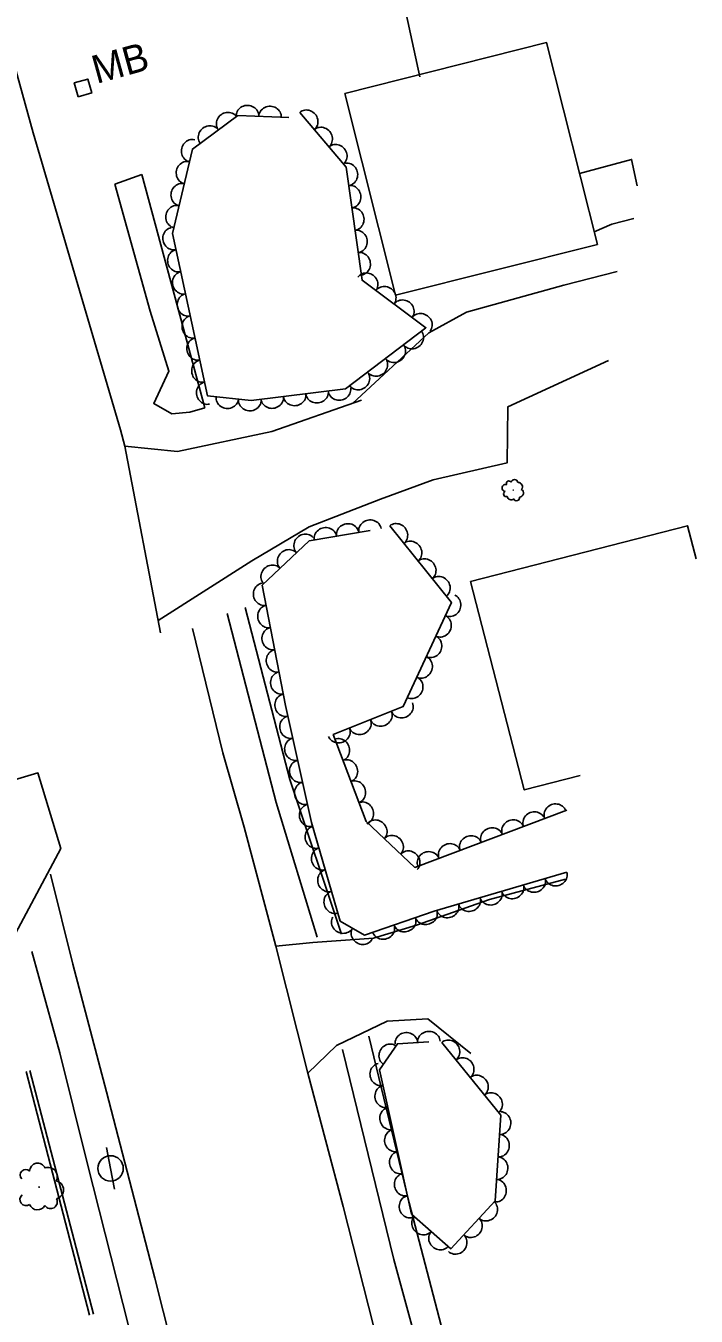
# Model space of a CAD drawing. Extents: x 1722896 to 1754269, y 648279 to 666297.
# Drawn here: x 1726025 to 1726143.8, y 664330.2 to 664558.8 of the extents above; entities that cross this region are included whole.
import ezdxf

# ---------------------------------------------------------------- set-up
doc = ezdxf.new("R2010")
doc.units = 0
for name, color, linetype in [('DESIGN - CENTERLINE - Proposed Text', 7, 'Continuous'), ('SURVEY - CENTERLINE - Preliminary', 7, 'Continuous'), ('SURVEY - CENTERLINE - Preliminary Text', 7, 'Continuous'), ('SURVEY - DTM - Breaklines', 7, 'Continuous'), ('SURVEY - VEGETATION - Features with Text', 7, 'Continuous')]:
    doc.layers.add(name, color=color, linetype=linetype)

msp = doc.modelspace()

# ---------------------------------------------------------------- linework, layer by layer
at = {"layer": 'DESIGN - CENTERLINE - Proposed Text'}
msp.add_line((1726035.11, 664547.81), (1726035.11, 664547.81), dxfattribs=at)
for points in [[(1726091, 664567.22), (1726094.81, 664549.72)], [(1726133.29, 664530.45), (1726132.3, 664535.12), (1726123.09, 664532.62)], [(1726125.7, 664522.26), (1726128.83, 664523.64), (1726132.69, 664524.67)], [(1726143.76, 664464.34), (1726142.24, 664470.24), (1726103.8, 664460.34), (1726113.31, 664423.43), (1726123.18, 664425.98)], [(1726025.03, 664373.56), (1726036.27, 664330.39)], [(1726025.73, 664373.73), (1726036.97, 664330.56)], [(1726025.74, 664373.63), (1726025.73, 664373.73)]]:
    msp.add_lwpolyline(points, dxfattribs=at)
for points in [[(1726081.52, 664546.81), (1726117.26, 664555.8), (1726126.25, 664520.06), (1726090.51, 664511.07)], [(1726034.25, 664546.22), (1726033.57, 664548.68), (1726035.98, 664549.34), (1726036.66, 664546.89)]]:
    msp.add_lwpolyline(points, close=True, dxfattribs=at)
at = {"layer": 'SURVEY - CENTERLINE - Preliminary'}
msp.add_lwpolyline([(1725991.19, 664443.09), (1726004.2, 664433.6), (1726008.98, 664427.22), (1726012.88, 664422.2), (1726027.13, 664426.44), (1726031.18, 664413.04), (1726020.27, 664392.69), (1726004.37, 664387.62), (1726008.07, 664375.49), (1726007.55, 664373.49), (1726007.26, 664372.95), (1726012.96, 664353.56), (1726017.88, 664335.55), (1726025.52, 664315.62)], dxfattribs=at)
at = {"layer": 'SURVEY - CENTERLINE - Preliminary Text'}
for points in [[(1725993.71, 664631.45), (1726000.55, 664608.01), (1726008.6, 664590.72), (1726016.13, 664572.76), (1726020.64, 664560.34), (1726026.29, 664539.82)], [(1726026.29, 664539.82), (1726033.91, 664513.93), (1726041.74, 664487.21), (1726042.55, 664484.34), (1726048.88, 664451.25)], [(1726040.74, 664530.7), (1726045.54, 664532.43)], [(1726056.69, 664491.1), (1726051.29, 664511.25), (1726045.54, 664532.43)], [(1726040.74, 664530.7), (1726047, 664508.26), (1726050.36, 664497.61), (1726047.66, 664491.86), (1726050.84, 664490.08), (1726054.08, 664490.35), (1726056.69, 664491.1)], [(1726082.84, 664491.91), (1726096.4, 664504.37), (1726103.05, 664508.03), (1726120.31, 664512.85), (1726129.76, 664515.28)], [(1726065.02, 664464.01), (1726075.2, 664470.02), (1726087.82, 664474.94), (1726097.15, 664478.36), (1726110.28, 664481.4), (1726110.37, 664491.28), (1726128.2, 664499.49)], [(1726042.56, 664484.3), (1726051.84, 664483.36), (1726068.55, 664486.94), (1726084.48, 664492.48)], [(1726048.45, 664453.46), (1726065.02, 664464.01)], [(1726060.67, 664454.66), (1726069.34, 664421.21), (1726076.59, 664397.38)], [(1726063.85, 664455.72), (1726071.76, 664425.3), (1726080.92, 664397.92)], [(1726054.55, 664452.02), (1726059.92, 664430.01), (1726063.68, 664416.85), (1726069.27, 664395.77), (1726074.98, 664373.29), (1726081.19, 664349.65), (1726085.72, 664332.02), (1726091.06, 664310.73), (1726094.47, 664298.9), (1726097.03, 664293.76), (1726101.24, 664290.95), (1726107.31, 664288.05), (1726111.1, 664287.57), (1726118.02, 664289.03), (1726122.29, 664290.41)], [(1726029.35, 664408.54), (1726033.35, 664392.59), (1726039.3, 664369.99), (1726047.86, 664336.97), (1726052.23, 664319.67), (1726056.15, 664304.39), (1726060.55, 664287.58), (1726065.98, 664266.15), (1726067.4, 664261.57), (1726069.43, 664253.18), (1726075.06, 664232.95), (1726081.66, 664207.25), (1726087.01, 664188.19), (1726090.33, 664176.23), (1726094.63, 664158.58), (1726099.65, 664137.39), (1726102.18, 664128.01), (1726103.96, 664121.22)], [(1726069.27, 664395.77), (1726075.82, 664396.43), (1726086.58, 664397.19), (1726094.19, 664399.51), (1726107.13, 664404.02), (1726120.62, 664407.63)], [(1726026.08, 664394.8), (1726031.02, 664376.89), (1726035.88, 664357.4), (1726043.26, 664328.28), (1726048.85, 664307.71)], [(1726074.98, 664373.29), (1726080.04, 664378.15), (1726088.99, 664382.5), (1726096.2, 664382.89), (1726103.81, 664376.76)], [(1726085.78, 664379.82), (1726092.88, 664350.28), (1726098.96, 664327.22), (1726103.1, 664309.13), (1726107.43, 664293.43)], [(1726081.11, 664377.47), (1726090.21, 664340.28), (1726098.22, 664310.83), (1726100.83, 664300.33), (1726095.42, 664298.86)]]:
    msp.add_lwpolyline(points, dxfattribs=at)
at = {"layer": 'SURVEY - DTM - Breaklines'}
for q in [(1726039.31, 664360.08), (1726040.72, 664352.71)]:
    msp.add_line((1726040.01, 664356.4), q, dxfattribs=at)
msp.add_circle((1726040.01, 664356.4), 2.25, dxfattribs=at)
at = {"layer": 'SURVEY - VEGETATION - Features with Text'}
for points in [[(1726073.51, 664543.44), (1726081.73, 664533.72), (1726084.57, 664513.71), (1726095.87, 664505.3), (1726081.65, 664494.47), (1726064.92, 664492.44), (1726057.21, 664493.23), (1726050.96, 664521.97), (1726054.52, 664536.94), (1726062.53, 664542.87), (1726071.6, 664542.52)], [(1726120.83, 664408.88), (1726097.35, 664401.98), (1726085, 664397.73), (1726080.66, 664400.21), (1726075.62, 664417.67), (1726071, 664438.41), (1726066.87, 664459.71), (1726075.21, 664467.54), (1726086.01, 664469.39)], [(1726089.47, 664470.22), (1726100.39, 664456.64), (1726091.87, 664438.2), (1726079.45, 664433.24), (1726085.28, 664417.83), (1726093.91, 664409.72), (1726120.86, 664419.85)], [(1726098.68, 664378.72), (1726109.14, 664365.85), (1726108.12, 664350.66), (1726100.3, 664342.16), (1726093.32, 664348.32), (1726087.68, 664373.84), (1726090.84, 664378.49), (1726096.4, 664378.8)]]:
    msp.add_lwpolyline(points, dxfattribs=at)
for centre, radius in [((1726111.35, 664476.54), 0.022), ((1726027.35, 664353.09), 0.0497)]:
    msp.add_circle(centre, radius, dxfattribs=at)
for centre, radius, start, end in [((1726109.99, 664476.92), 0.629, 70.3934, 263.8131), ((1726110.58, 664477.73), 0.433, 30.3727, 209.1184), ((1726111.56, 664477.78), 0.631, 8.2566, 165.0455), ((1726112.25, 664477.16), 0.719, 317.3093, 94.8335), ((1726110.11, 664475.86), 0.479, 113.0121, 290.3312), ((1726110.95, 664475.5), 0.679, 188.2991, 315.1448), ((1726111.93, 664475.19), 0.527, 198.458, 13.4583), ((1726112.46, 664476.03), 0.714, 268.2051, 64.0436), ((1726024.98, 664355.23), 0.978, 45.1099, 223.8555), ((1726027.09, 664355.92), 1.42, 22.9937, 179.7826), ((1726028.94, 664354.95), 1.62, 332.0465, 109.5707), ((1726030.06, 664352.61), 1.61, 282.9423, 78.7808), ((1726025.03, 664350.88), 1.08, 127.7492, 305.0684), ((1726027.06, 664350.59), 1.53, 203.0363, 329.882), ((1726029.38, 664350.47), 1.19, 213.1952, 28.1955)]:
    msp.add_arc(centre, radius, start, end, dxfattribs=at)
for centre, major_axis in [((1726060.71, 664541.52), (1.61, 1.19)), ((1726064.26, 664542.8), (2, -0.08)), ((1726068.26, 664542.65), (2, -0.08)), ((1726074.81, 664541.92), (1.29, -1.53)), ((1726057.5, 664539.14), (1.61, 1.19)), ((1726077.39, 664538.86), (1.29, -1.53)), ((1726054.45, 664536.65), (0.46, 1.95)), ((1726079.97, 664535.81), (1.29, -1.53)), ((1726053.53, 664532.76), (0.46, 1.95)), ((1726081.91, 664532.46), (0.28, -1.98)), ((1726052.6, 664528.86), (0.46, 1.95)), ((1726082.47, 664528.5), (0.28, -1.98)), ((1726051.67, 664524.97), (0.46, 1.95)), ((1726083.03, 664524.54), (0.28, -1.98)), ((1726051.15, 664521.08), (-0.43, 1.95)), ((1726083.6, 664520.58), (0.28, -1.98)), ((1726052, 664517.17), (-0.43, 1.95)), ((1726084.16, 664516.62), (0.28, -1.98)), ((1726052.85, 664513.26), (-0.43, 1.95)), ((1726085.42, 664513.08), (1.6, -1.19)), ((1726088.63, 664510.69), (1.6, -1.19)), ((1726053.7, 664509.35), (-0.43, 1.95)), ((1726091.84, 664508.3), (1.6, -1.19)), ((1726054.55, 664505.45), (-0.43, 1.95)), ((1726095.04, 664505.91), (1.6, -1.19)), ((1726093.5, 664503.49), (-1.59, -1.21)), ((1726055.4, 664501.54), (-0.43, 1.95)), ((1726090.32, 664501.07), (-1.59, -1.21)), ((1726056.26, 664497.63), (-0.43, 1.95)), ((1726087.14, 664498.65), (-1.59, -1.21)), ((1726057.11, 664493.72), (-0.43, 1.95)), ((1726083.96, 664496.23), (-1.59, -1.21)), ((1726072.62, 664493.38), (-1.99, -0.24)), ((1726076.59, 664493.86), (-1.99, -0.24)), ((1726080.56, 664494.34), (-1.99, -0.24)), ((1726060.69, 664492.87), (-1.99, 0.2)), ((1726064.67, 664492.47), (-1.99, 0.2)), ((1726068.64, 664492.9), (-1.99, -0.24)), ((1726082.02, 664468.71), (1.97, 0.34)), ((1726085.96, 664469.39), (1.97, 0.34)), ((1726090.72, 664468.66), (1.25, -1.56)), ((1726074.42, 664466.8), (1.46, 1.37)), ((1726078.08, 664468.03), (1.97, 0.34)), ((1726071.5, 664464.06), (1.46, 1.37)), ((1726093.23, 664465.54), (1.25, -1.56)), ((1726095.74, 664462.42), (1.25, -1.56)), ((1726068.59, 664461.32), (1.46, 1.37)), ((1726098.25, 664459.31), (1.25, -1.56)), ((1726067.19, 664458.09), (-0.38, 1.96)), ((1726100.15, 664456.12), (-0.84, -1.82)), ((1726067.95, 664454.16), (-0.38, 1.96)), ((1726068.71, 664450.24), (-0.38, 1.96)), ((1726098.47, 664452.49), (-0.84, -1.82)), ((1726096.79, 664448.85), (-0.84, -1.82)), ((1726069.47, 664446.31), (-0.38, 1.96)), ((1726095.12, 664445.22), (-0.84, -1.82)), ((1726070.23, 664442.38), (-0.38, 1.96)), ((1726093.44, 664441.59), (-0.84, -1.82)), ((1726070.99, 664438.45), (-0.38, 1.96)), ((1726091.63, 664438.1), (-1.86, -0.74)), ((1726071.86, 664434.55), (-0.44, 1.95)), ((1726087.91, 664436.62), (-1.86, -0.74)), ((1726080.48, 664433.65), (-1.86, -0.74)), ((1726084.2, 664435.14), (-1.86, -0.74)), ((1726072.73, 664430.65), (-0.44, 1.95)), ((1726080.47, 664430.54), (0.71, -1.87)), ((1726073.6, 664426.74), (-0.44, 1.95)), ((1726081.89, 664426.8), (0.71, -1.87)), ((1726074.47, 664422.84), (-0.44, 1.95)), ((1726083.3, 664423.06), (0.71, -1.87)), ((1726075.34, 664418.93), (-0.44, 1.95)), ((1726084.72, 664419.32), (0.71, -1.87)), ((1726118.78, 664419.07), (1.87, 0.7)), ((1726087.04, 664416.18), (1.46, -1.37)), ((1726111.29, 664416.25), (1.87, 0.7)), ((1726115.03, 664417.66), (1.87, 0.7)), ((1726076.37, 664415.07), (-0.55, 1.92)), ((1726089.95, 664413.44), (1.46, -1.37)), ((1726103.8, 664413.44), (1.87, 0.7)), ((1726107.54, 664414.85), (1.87, 0.7)), ((1726100.06, 664412.03), (1.87, 0.7)), ((1726077.48, 664411.23), (-0.55, 1.92)), ((1726092.87, 664410.7), (1.46, -1.37)), ((1726096.31, 664410.62), (1.87, 0.7)), ((1726078.59, 664407.38), (-0.55, 1.92)), ((1726118.92, 664408.32), (-1.92, -0.56)), ((1726111.24, 664406.06), (-1.92, -0.56)), ((1726115.08, 664407.19), (-1.92, -0.56)), ((1726079.7, 664403.54), (-0.55, 1.92)), ((1726103.57, 664403.81), (-1.92, -0.56)), ((1726107.4, 664404.94), (-1.92, -0.56)), ((1726095.91, 664401.49), (-1.89, -0.65)), ((1726099.73, 664402.68), (-1.92, -0.56)), ((1726081.12, 664399.94), (-1.74, 0.99)), ((1726092.13, 664400.19), (-1.89, -0.65)), ((1726084.6, 664397.97), (-1.74, 0.99)), ((1726088.35, 664398.88), (-1.89, -0.65)), ((1726092.41, 664378.58), (2, 0.11)), ((1726096.4, 664378.8), (2, 0.11)), ((1726099.95, 664377.17), (1.26, -1.55)), ((1726089.47, 664376.48), (1.12, 1.65)), ((1726087.85, 664373.05), (-0.43, 1.95)), ((1726102.47, 664374.06), (1.26, -1.55)), ((1726104.99, 664370.96), (1.26, -1.55)), ((1726088.72, 664369.15), (-0.43, 1.95)), ((1726107.51, 664367.85), (1.26, -1.55)), ((1726089.58, 664365.24), (-0.43, 1.95)), ((1726109.04, 664364.43), (-0.13, -2)), ((1726090.44, 664361.34), (-0.43, 1.95)), ((1726108.77, 664360.44), (-0.13, -2)), ((1726091.31, 664357.43), (-0.43, 1.95)), ((1726108.51, 664356.45), (-0.13, -2)), ((1726092.17, 664353.53), (-0.43, 1.95)), ((1726108.24, 664352.46), (-0.13, -2)), ((1726093.03, 664349.62), (-0.43, 1.95)), ((1726106.63, 664349.04), (-1.35, -1.47)), ((1726095.32, 664346.55), (-1.5, 1.32)), ((1726103.93, 664346.1), (-1.35, -1.47)), ((1726098.32, 664343.91), (-1.5, 1.32)), ((1726101.22, 664343.15), (-1.35, -1.47))]:
    msp.add_ellipse(centre, major_axis=major_axis, ratio=0.940188, start_param=0, end_param=3.141593, dxfattribs=at)

# ---------------------------------------------------------------- texts
at = {"layer": 'DESIGN - CENTERLINE - Proposed Text'}
msp.add_text('MB', height=5, rotation=15.4174, dxfattribs=at).set_placement((1726037.52, 664548.47))

doc.saveas('drawing.dxf')
